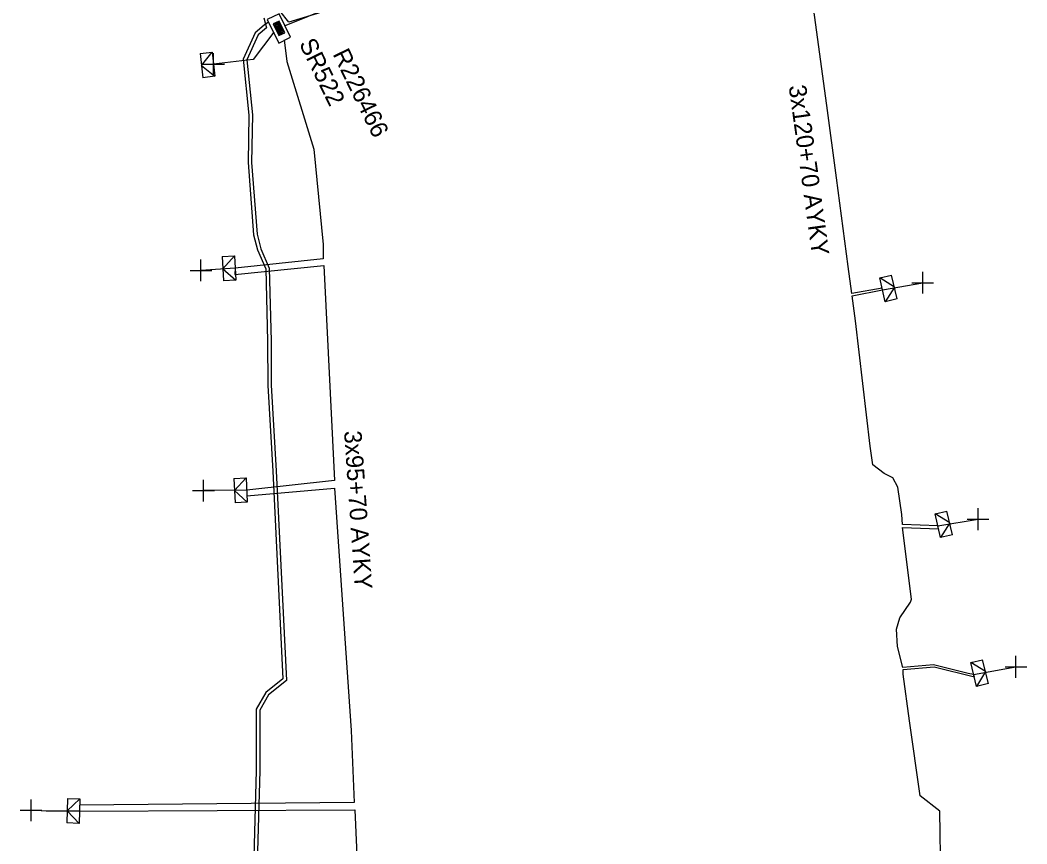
# Model space of a CAD drawing. Extents: x -544780 to -541582, y -1198995 to -1196551.
# Drawn here: x -542670.3 to -542612.6, y -1198302.1 to -1198255 of the extents above; entities that cross this region are included whole.
import ezdxf

# ---------------------------------------------------------------- set-up
doc = ezdxf.new("R2010")
doc.units = 0
for name, color, linetype in [('Vrstva 1', 7, 'Continuous'), ('Vrstva 28', 7, 'Continuous'), ('Vrstva 29', 7, 'Continuous'), ('Vrstva 30', 7, 'Continuous'), ('Vrstva 31', 7, 'Continuous'), ('Vrstva 34', 7, 'Continuous'), ('Vrstva 5', 7, 'Continuous'), ('Vrstva 52', 7, 'Continuous'), ('Vrstva 59', 7, 'Continuous'), ('Vrstva 6', 7, 'Continuous'), ('Vrstva 8', 7, 'Continuous'), ('Vrstva 9', 7, 'Continuous')]:
    doc.layers.add(name, color=color, linetype=linetype)

# ---------------------------------------------------------------- blocks, each defined once
blk = doc.blocks.new('NN800')
at = {"layer": 'Vrstva 1'}
for points in [[(-0.442, 0.442), (0.442, -0.442)], [(-0.442, -0.442), (0.442, 0.442)]]:
    blk.add_lwpolyline(points, dxfattribs=at)
blk = doc.blocks.new('NN620')
at = {"layer": 'Vrstva 8'}
for points in [[(0.752, 0.004), (-0.748, 0.004)], [(-0.748, 0.004), (-0.748, -0.746)], [(0.752, -0.746), (0.752, 0.004)], [(0.368, -0.18), (-0.376, -0.18)], [(-0.376, -0.18), (-0.376, -0.558)], [(-0.376, -0.558), (0.368, -0.558)], [(0.321, -0.227), (-0.329, -0.227)], [(-0.329, -0.227), (-0.329, -0.51)], [(-0.329, -0.51), (0.321, -0.51)], [(0.274, -0.274), (-0.281, -0.274)], [(-0.281, -0.274), (-0.281, -0.463)], [(-0.281, -0.463), (0.274, -0.463)], [(0.227, -0.321), (-0.234, -0.321)], [(-0.234, -0.321), (-0.234, -0.416)], [(-0.234, -0.416), (0.227, -0.416)], [(-0.193, -0.369), (0.185, -0.369)], [(0.227, -0.416), (0.227, -0.321)], [(0.274, -0.463), (0.274, -0.274)], [(0.321, -0.51), (0.321, -0.227)], [(0.368, -0.558), (0.368, -0.18)], [(-0.748, -0.746), (0.752, -0.746)]]:
    blk.add_lwpolyline(points, dxfattribs=at)
blk = doc.blocks.new('NN630')
at = {"layer": 'Vrstva 9'}
for points in [[(-0.003, -0.7), (-0.703, 0)], [(-0.703, -0.7), (-0.703, 0), (0.697, 0), (0.697, -0.7)], [(-0.003, -0.7), (0.697, 0)], [(-0.703, -0.7), (0.697, -0.7)]]:
    blk.add_lwpolyline(points, dxfattribs=at)

msp = doc.modelspace()

# ---------------------------------------------------------------- linework, layer by layer
at = {"layer": 'Vrstva 5'}
for points in [[(-542652.825, -1198208.639), (-542653.426, -1198208.878), (-542653.745, -1198209.636), (-542653.606, -1198210.814), (-542653.167, -1198212.371), (-542651.411, -1198217.557), (-542649.875, -1198222.319), (-542649.835, -1198222.858), (-542650.174, -1198223.237), (-542655.84, -1198225.433), (-542656.18, -1198225.892), (-542656.738, -1198227.862), (-542656.359, -1198230.138), (-542655.761, -1198237.458), (-542655.202, -1198243.999), (-542654.843, -1198248.061), (-542654.583, -1198249), (-542653.586, -1198250.018), (-542651.91, -1198253.106), (-542651.91, -1198253.625), (-542652.389, -1198254.184), (-542655.137, -1198255.292)], [(-542617.487, -1198304.103), (-542617.55, -1198300.265), (-542618.676, -1198299.401), (-542619.286, -1198295.102), (-542619.643, -1198292.42), (-542619.655, -1198292.165), (-542617.881, -1198292.014), (-542615.565, -1198292.585), (-542615.611, -1198292.44), (-542615.918, -1198292.393), (-542617.907, -1198291.899), (-542619.668, -1198292.051), (-542619.986, -1198290.833), (-542620.037, -1198289.84), (-542619.846, -1198289.204), (-542619.223, -1198288.3), (-542619.172, -1198288.125), (-542619.681, -1198284.018), (-542617.623, -1198284.095), (-542617.665, -1198283.918), (-542619.693, -1198283.84), (-542619.732, -1198283.267), (-542619.948, -1198281.718), (-542620.253, -1198281.17), (-542620.749, -1198280.928), (-542621.386, -1198280.435), (-542621.551, -1198279.366), (-542622.391, -1198272.171), (-542622.585, -1198270.747), (-542620.839, -1198270.399), (-542620.855, -1198270.301), (-542622.602, -1198270.623), (-542622.811, -1198269.066), (-542623.472, -1198263.995), (-542624.019, -1198259.84), (-542624.91, -1198253.381)], [(-542652.149, -1198254.247), (-542654.863, -1198255.061), (-542655.382, -1198254.422)], [(-542656.031, -1198255.076), (-542656.288, -1198255.246), (-542656.802, -1198255.675), (-542657.481, -1198257.184), (-542657.16, -1198260.388), (-542657.21, -1198263.106), (-542656.888, -1198267.254), (-542656.659, -1198268.116), (-542656.189, -1198269.204), (-542656.09, -1198273.343), (-542656.08, -1198275.876), (-542655.79, -1198280.791), (-542655.207, -1198292.691), (-542656.195, -1198293.479), (-542656.739, -1198294.437), (-542656.739, -1198297.94), (-542657.038, -1198308.53)], [(-542656.299, -1198254.821), (-542656.16, -1198255.4), (-542656.639, -1198255.799), (-542657.277, -1198257.217), (-542656.96, -1198260.38), (-542657.01, -1198263.1), (-542656.69, -1198267.22), (-542656.47, -1198268.05), (-542655.99, -1198269.16), (-542655.89, -1198273.34), (-542655.88, -1198275.87), (-542655.59, -1198280.78), (-542655.002, -1198292.784), (-542656.04, -1198293.611), (-542656.539, -1198294.49), (-542656.539, -1198297.943), (-542656.838, -1198308.535)], [(-542655.144, -1198256.07), (-542654.981, -1198257.314), (-542653.43, -1198262.341), (-542652.903, -1198267.802), (-542652.903, -1198268.628), (-542657.948, -1198269.16), (-542657.958, -1198269.528), (-542652.872, -1198269.001), (-542652.252, -1198281.335), (-542657.288, -1198281.878), (-542657.28, -1198282.216), (-542652.252, -1198281.77), (-542651.29, -1198295.653), (-542651.125, -1198299.779), (-542666.875, -1198299.936), (-542666.875, -1198300.277), (-542651.087, -1198300.201), (-542650.701, -1198308.848), (-542650.36, -1198313.937), (-542650.174, -1198316.388), (-542649.74, -1198328.438), (-542654.981, -1198328.469), (-542654.921, -1198329.515)]]:
    msp.add_lwpolyline(points, dxfattribs=at)
at = {"layer": 'Vrstva 52'}
msp.add_lwpolyline([(-542655.727, -1198255.632), (-542656.92, -1198257.2), (-542659.186, -1198257.476)], dxfattribs=at)
at = {"layer": 'Vrstva 59'}
for points in [[(-542657.948, -1198269.16), (-542659.91, -1198269.288)], [(-542620.839, -1198270.399), (-542618.531, -1198269.997)], [(-542657.288, -1198281.878), (-542659.762, -1198281.907)], [(-542617.665, -1198283.918), (-542615.357, -1198283.547)], [(-542615.611, -1198292.44), (-542613.185, -1198292.001)], [(-542666.875, -1198300.277), (-542668.778, -1198300.282), (-542669.651, -1198300.222)]]:
    msp.add_lwpolyline(points, dxfattribs=at)

# ---------------------------------------------------------------- block references
at = {"layer": 'Vrstva 28', "rotation": -64.04013889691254}
msp.add_blockref('NN620', (-542655.107, -1198255.26), dxfattribs=at)
at = {"layer": 'Vrstva 31'}
for p, rotation in [((-542659.186, -1198257.476), -83.36868063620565), ((-542657.948, -1198269.16), -86.93512222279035), ((-542620.839, -1198270.399), 103.21258330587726), ((-542657.288, -1198281.878), -87.56526943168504), ((-542617.665, -1198283.918), 103.21178890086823), ((-542615.611, -1198292.44), 103.87178604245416), ((-542666.875, -1198300.277), -91.92011109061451)]:
    msp.add_blockref('NN630', p, dxfattribs=dict(at, rotation=rotation))
at = {"layer": 'Vrstva 34'}
for p, rotation in [((-542659.186, -1198257.476), 45), ((-542659.91, -1198269.288), 45.00000009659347), ((-542618.531, -1198269.997), 45), ((-542659.762, -1198281.907), 45), ((-542615.357, -1198283.547), 45), ((-542613.185, -1198292.001), 45), ((-542669.651, -1198300.222), 44.99999995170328)]:
    msp.add_blockref('NN800', p, dxfattribs=dict(at, rotation=rotation))

# ---------------------------------------------------------------- texts
at = {"layer": 'Vrstva 29'}
msp.add_text('R226466', height=1, rotation=295.96, dxfattribs=at).set_placement((-542652.378, -1198256.891))
at = {"layer": 'Vrstva 30'}
msp.add_text('SR522', height=1, rotation=295.96, dxfattribs=at).set_placement((-542654.304, -1198256.289))
at = {"layer": 'Vrstva 6'}
for s, rotation, p in [('3x120+70 AYKY', 277.854, (-542626.218, -1198258.728)), ('3x95+70 AYKY', 273.964, (-542651.709, -1198278.503))]:
    msp.add_text(s, height=1, rotation=rotation, dxfattribs=at).set_placement(p)

doc.saveas('drawing.dxf')
